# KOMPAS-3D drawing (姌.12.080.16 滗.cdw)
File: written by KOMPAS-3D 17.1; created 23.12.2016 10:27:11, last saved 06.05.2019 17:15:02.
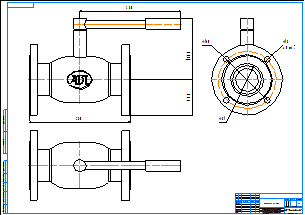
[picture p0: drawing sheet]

Sheet 1: A1, landscape

Title block, sheet 1: name: КШ.12.080.16 фф; material: Внимание! Данный продукт является объектом авторского права ООО «Торговый Дом АДЛ». / Запрещается изменение, копирование, распространение / (в том числе путем копирования на другие сайты и ресурсы в Интернете) / или любое иное использование информации и объектов без предварительного / согласия правообладателя (ООО «Торговый Дом АДЛ»).; sheets: 1; organisation: ООО "Торговый дом АДЛ"; sheet format: A1; stored path: C:\Users\tra\Desktop\2д чертежи\Шаровые краны БИВАЛ\КШ_Бивал_серия_11_12\KOMPAS_2D\КШ.12.080.16 фф.cdw

Views: Вид 1, Проекционный вид 2, Проекционный вид 3
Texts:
  Klimkovich
  ADL
Dimensions and other numbers on the sheet: 280; 168,8; 97,5; 160; 81; 18; 4 Отв.; 1:1; 1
